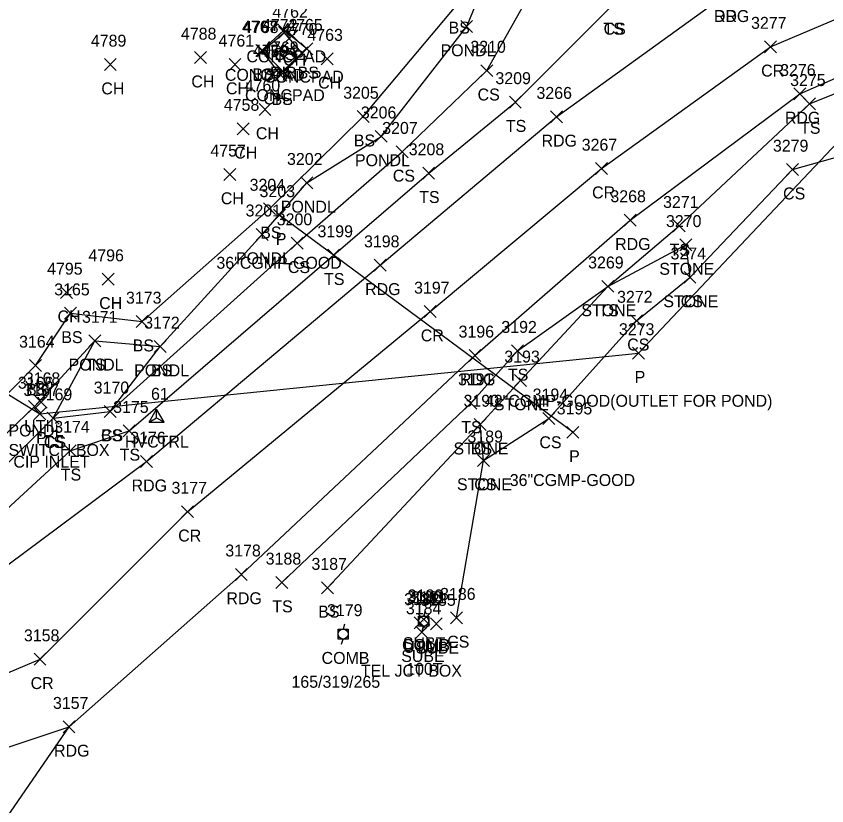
# Model space of a CAD drawing. Extents: x 49137 to 50946, y 9590 to 10709.
# Drawn here: x 50177.5 to 50313.3, y 9667.4 to 9799.7 of the extents above; entities that cross this region are included whole.
import ezdxf

# ---------------------------------------------------------------- set-up
doc = ezdxf.new("R2010")
doc.units = 0
for name, color, linetype in [('C_A', 7, 'Continuous'), ('C_I', 7, 'Continuous'), ('CPSM', 7, 'Continuous'), ('D_A', 7, 'Continuous'), ('D_C', 7, 'Continuous'), ('D_I', 7, 'Continuous'), ('D_TIC', 7, 'Continuous'), ('DCP', 7, 'Continuous'), ('L_A', 7, 'Continuous'), ('L_I', 7, 'Continuous'), ('L_TIC', 7, 'Continuous'), ('LASF', 7, 'Continuous'), ('LAWE', 7, 'Continuous'), ('LELB', 7, 'Continuous'), ('LS', 7, 'Continuous'), ('P_A', 7, 'Continuous'), ('P_I', 7, 'Continuous'), ('P_TIC', 7, 'Continuous'), ('PEU', 7, 'Continuous'), ('PRC', 7, 'Continuous'), ('R_A', 7, 'Continuous'), ('U_A', 7, 'Continuous'), ('U_C', 7, 'Continuous'), ('U_I', 7, 'Continuous'), ('U_TIC', 7, 'Continuous'), ('UDEFAULT', 7, 'Continuous'), ('UP', 7, 'Continuous')]:
    doc.layers.add(name, color=color, linetype=linetype)

msp = doc.modelspace()

# ---------------------------------------------------------------- linework, layer by layer
at = {"layer": 'CPSM'}
for p, q in [((50199.74, 9731.73), (50200.99, 9733.9)), ((50202.24, 9731.73), (50200.99, 9733.9)), ((50200.99, 9732.46), (50200.99, 9733.9)), ((50199.74, 9731.73), (50200.99, 9732.46)), ((50199.74, 9731.73), (50202.24, 9731.73)), ((50200.99, 9732.46), (50200.99, 9732.46)), ((50200.99, 9732.46), (50202.24, 9731.73))]:
    msp.add_line(p, q, dxfattribs=at)
at = {"layer": 'D_TIC'}
for points in [[(50220.91, 9793.29), (50222.91, 9795.29)], [(50222.91, 9793.29), (50220.91, 9795.29)], [(50220.58, 9765.42), (50222.58, 9767.42)], [(50222.58, 9765.42), (50220.58, 9767.42)], [(50280.74, 9742.29), (50282.74, 9744.29)], [(50282.74, 9742.29), (50280.74, 9744.29)], [(50180.4, 9732.09), (50182.4, 9734.09)], [(50182.4, 9732.09), (50180.4, 9734.09)], [(50269.76, 9729.01), (50271.76, 9731.01)], [(50271.76, 9729.01), (50269.76, 9731.01)]]:
    msp.add_lwpolyline(points, dxfattribs=at)
at = {"layer": 'DCP'}
for points in [[(49941.69, 9827.48), (50059.34, 9808.37), (50181.4, 9733.09), (50281.74, 9743.29), (50422.72, 9892.52), (50122.34, 10663.61), (50179.93, 10552.61), (50179.64, 10394.45), (50122.34, 10285.07), (50121.56, 10284.35)], [(50270.76, 9730.01), (50221.58, 9766.42)]]:
    msp.add_lwpolyline(points, dxfattribs=at)
at = {"layer": 'L_TIC'}
for points in [[(50221.31, 9796.39), (50223.31, 9798.39)], [(50223.31, 9796.39), (50221.31, 9798.39)], [(50221.39, 9796.01), (50223.39, 9798.01)], [(50223.39, 9796.01), (50221.39, 9798.01)], [(50221.39, 9796.01), (50223.39, 9798.01)], [(50223.39, 9796.01), (50221.39, 9798.01)], [(50251.96, 9797.03), (50253.96, 9799.03)], [(50253.96, 9797.03), (50251.96, 9799.03)], [(50222.7, 9795.48), (50224.7, 9797.48)], [(50224.7, 9795.48), (50222.7, 9797.48)], [(50225.18, 9793.29), (50227.18, 9795.29)], [(50227.18, 9793.29), (50225.18, 9795.29)], [(50207.32, 9791.81), (50209.32, 9793.81)], [(50209.32, 9791.81), (50207.32, 9793.81)], [(50217.61, 9793), (50219.61, 9795)], [(50219.61, 9793), (50217.61, 9795)], [(50217.61, 9793), (50219.61, 9795)], [(50219.61, 9793), (50217.61, 9795)], [(50217.79, 9792.92), (50219.79, 9794.92)], [(50219.79, 9792.92), (50217.79, 9794.92)], [(50217.79, 9792.92), (50219.79, 9794.92)], [(50219.79, 9792.92), (50217.79, 9794.92)], [(50224.34, 9792.61), (50226.34, 9794.61)], [(50226.34, 9792.61), (50224.34, 9794.61)], [(50192.23, 9790.64), (50194.23, 9792.64)], [(50194.23, 9790.64), (50192.23, 9792.64)], [(50213.12, 9790.66), (50215.12, 9792.66)], [(50215.12, 9790.66), (50213.12, 9792.66)], [(50228.57, 9791.62), (50230.57, 9793.62)], [(50230.57, 9791.62), (50228.57, 9793.62)], [(50221.15, 9789.51), (50223.15, 9791.51)], [(50223.15, 9789.51), (50221.15, 9791.51)], [(50255.35, 9789.62), (50257.35, 9791.62)], [(50257.35, 9789.62), (50255.35, 9791.62)], [(50219.39, 9788.95), (50221.39, 9790.95)], [(50221.39, 9788.95), (50219.39, 9790.95)], [(50220.81, 9788.87), (50222.81, 9790.87)], [(50222.81, 9788.87), (50220.81, 9790.87)], [(50220.81, 9788.87), (50222.81, 9790.87)], [(50222.81, 9788.87), (50220.81, 9790.87)], [(50260.12, 9784.36), (50262.12, 9786.36)], [(50262.12, 9784.36), (50260.12, 9786.36)], [(50309.44, 9784.04), (50311.44, 9786.04)], [(50311.44, 9784.04), (50309.44, 9786.04)], [(50218.15, 9783.13), (50220.15, 9785.13)], [(50220.15, 9783.13), (50218.15, 9785.13)], [(50234.59, 9781.92), (50236.59, 9783.92)], [(50236.59, 9781.92), (50234.59, 9783.92)], [(50214.51, 9779.89), (50216.51, 9781.89)], [(50216.51, 9779.89), (50214.51, 9781.89)], [(50237.61, 9778.61), (50239.61, 9780.61)], [(50239.61, 9778.61), (50237.61, 9780.61)], [(50241.13, 9776.02), (50243.13, 9778.02)], [(50243.13, 9776.02), (50241.13, 9778.02)], [(50306.56, 9773.04), (50308.56, 9775.04)], [(50308.56, 9773.04), (50306.56, 9775.04)], [(50212.26, 9772.23), (50214.26, 9774.23)], [(50214.26, 9772.23), (50212.26, 9774.23)], [(50245.59, 9772.44), (50247.59, 9774.44)], [(50247.59, 9772.44), (50245.59, 9774.44)], [(50225.18, 9770.82), (50227.18, 9772.82)], [(50227.18, 9770.82), (50225.18, 9772.82)], [(50218.91, 9766.49), (50220.91, 9768.49)], [(50220.91, 9766.49), (50218.91, 9768.49)], [(50287.57, 9763.61), (50289.57, 9765.61)], [(50289.57, 9763.61), (50287.57, 9765.61)], [(50217.67, 9762.18), (50219.67, 9764.18)], [(50219.67, 9762.18), (50217.67, 9764.18)], [(50223.55, 9760.7), (50225.55, 9762.7)], [(50225.55, 9760.7), (50223.55, 9762.7)], [(50288.71, 9760.41), (50290.71, 9762.41)], [(50290.71, 9760.41), (50288.71, 9762.41)], [(50229.66, 9758.7), (50231.66, 9760.7)], [(50231.66, 9758.7), (50229.66, 9760.7)], [(50191.87, 9754.67), (50193.87, 9756.67)], [(50193.87, 9754.67), (50191.87, 9756.67)], [(50289.39, 9754.98), (50291.39, 9756.98)], [(50291.39, 9754.98), (50289.39, 9756.98)], [(50289.39, 9754.98), (50291.39, 9756.98)], [(50291.39, 9754.98), (50289.39, 9756.98)], [(50184.89, 9752.43), (50186.89, 9754.43)], [(50186.89, 9752.43), (50184.89, 9754.43)], [(50275.63, 9753.47), (50277.63, 9755.47)], [(50277.63, 9753.47), (50275.63, 9755.47)], [(50275.63, 9753.47), (50277.63, 9755.47)], [(50277.63, 9753.47), (50275.63, 9755.47)], [(50185.56, 9748.96), (50187.56, 9750.96)], [(50187.56, 9748.96), (50185.56, 9750.96)], [(50197.54, 9747.57), (50199.54, 9749.57)], [(50199.54, 9747.57), (50197.54, 9749.57)], [(50280.43, 9747.72), (50282.43, 9749.72)], [(50282.43, 9747.72), (50280.43, 9749.72)], [(50189.61, 9744.36), (50191.61, 9746.36)], [(50191.61, 9744.36), (50189.61, 9746.36)], [(50189.61, 9744.36), (50191.61, 9746.36)], [(50191.61, 9744.36), (50189.61, 9746.36)], [(50200.6, 9743.39), (50202.6, 9745.39)], [(50202.6, 9743.39), (50200.6, 9745.39)], [(50200.6, 9743.39), (50202.6, 9745.39)], [(50202.6, 9743.39), (50200.6, 9745.39)], [(50260.46, 9742.67), (50262.46, 9744.67)], [(50262.46, 9742.67), (50260.46, 9744.67)], [(50179.67, 9740.2), (50181.67, 9742.2)], [(50181.67, 9740.2), (50179.67, 9742.2)], [(50260.97, 9737.7), (50262.97, 9739.7)], [(50262.97, 9737.7), (50260.97, 9739.7)], [(50252.64, 9733.88), (50254.64, 9735.88)], [(50254.64, 9733.88), (50252.64, 9735.88)], [(50179.53, 9733.32), (50181.53, 9735.32)], [(50181.53, 9733.32), (50179.53, 9735.32)], [(50192.22, 9732.51), (50194.22, 9734.51)], [(50194.22, 9732.51), (50192.22, 9734.51)], [(50192.22, 9732.51), (50194.22, 9734.51)], [(50194.22, 9732.51), (50192.22, 9734.51)], [(50182.65, 9731.38), (50184.65, 9733.38)], [(50184.65, 9731.38), (50182.65, 9733.38)], [(50182.65, 9731.38), (50184.65, 9733.38)], [(50184.65, 9731.38), (50182.65, 9733.38)], [(50265.71, 9731.34), (50267.71, 9733.34)], [(50267.71, 9731.34), (50265.71, 9733.34)], [(50195.39, 9729.26), (50197.39, 9731.26)], [(50197.39, 9729.26), (50195.39, 9731.26)], [(50254.2, 9730.3), (50256.2, 9732.3)], [(50256.2, 9730.3), (50254.2, 9732.3)], [(50254.2, 9730.3), (50256.2, 9732.3)], [(50256.2, 9730.3), (50254.2, 9732.3)], [(50185.51, 9725.93), (50187.51, 9727.93)], [(50187.51, 9725.93), (50185.51, 9727.93)], [(50254.79, 9724.3), (50256.79, 9726.3)], [(50256.79, 9724.3), (50254.79, 9726.3)], [(50254.79, 9724.3), (50256.79, 9726.3)], [(50256.79, 9724.3), (50254.79, 9726.3)], [(50220.97, 9703.84), (50222.97, 9705.84)], [(50222.97, 9703.84), (50220.97, 9705.84)], [(50228.63, 9702.96), (50230.63, 9704.96)], [(50230.63, 9702.96), (50228.63, 9704.96)], [(50250.25, 9697.93), (50252.25, 9699.93)], [(50252.25, 9697.93), (50250.25, 9699.93)]]:
    msp.add_lwpolyline(points, dxfattribs=at)
at = {"layer": 'LASF'}
msp.add_lwpolyline([(50255.79, 9725.3), (50255.2, 9731.3), (50261.97, 9738.7), (50276.63, 9754.47), (50289.71, 9761.41), (50290.39, 9755.98)], dxfattribs=at)
at = {"layer": 'LAWE'}
msp.add_lwpolyline([(50126.73, 9813.77), (50124.61, 9796.89), (50111.25, 9777.04), (50110.47, 9750.09), (50103.82, 9729.7), (50104.43, 9724.64), (50098.48, 9698.71), (50117.09, 9681.54), (50135.81, 9695.39), (50163.01, 9717.6), (50180.53, 9734.32), (50190.61, 9745.36), (50201.6, 9744.39), (50218.67, 9763.18), (50226.18, 9771.82), (50238.61, 9779.61), (50252.96, 9798.03), (50263.09, 9822.8), (50257.66, 9841.25), (50250.32, 9860.86)], dxfattribs=at)
at = {"layer": 'LELB'}
for points in [[(49989.46, 9641.11), (50017.53, 9654.36), (50065.13, 9666.04), (50092.49, 9669.85), (50112.07, 9676.7), (50119.45, 9680.62), (50138.81, 9692.31), (50165.23, 9714.09), (50183.65, 9732.38), (50193.22, 9733.51), (50224.55, 9761.7), (50242.13, 9777.02), (50256.35, 9790.62), (50269.01, 9813.23), (50267.22, 9836.46), (50262.07, 9851.46), (50256.24, 9864.61)], [(50130.08, 9813.38), (50127.49, 9796.45), (50115.24, 9773.32), (50112.63, 9748.12), (50107.86, 9731.67), (50105.33, 9723.23), (50101.67, 9703.92), (50120.36, 9686.99), (50133.96, 9697.22), (50159.53, 9719.77), (50180.67, 9741.2), (50186.56, 9749.96), (50198.54, 9748.57), (50219.91, 9767.49), (50235.59, 9782.92), (50251.48, 9801.83), (50259.82, 9821.36), (50255.17, 9839.31), (50246.31, 9858.9)], [(50106.75, 9669.47), (50141.52, 9690.01), (50167.92, 9709.84), (50186.51, 9726.93), (50196.39, 9730.26), (50230.66, 9759.7), (50246.59, 9773.44), (50261.12, 9785.36), (50277.47, 9801.65), (50284.03, 9806.08), (50295.89, 9825.75), (50301.66, 9836.3), (50304.52, 9848.49)], [(50221.81, 9789.87), (50226.18, 9794.29), (50222.31, 9797.39), (50218.61, 9794)], [(50221.81, 9789.87), (50218.61, 9794)], [(50221.97, 9704.84), (50253.64, 9734.88), (50261.46, 9743.67), (50276.63, 9754.47), (50288.57, 9764.61), (50310.44, 9785.04), (50329.97, 9792.93), (50346.68, 9794.33)], [(50251.25, 9698.93), (50255.79, 9725.3), (50266.71, 9732.34), (50281.43, 9748.72), (50290.39, 9755.98), (50307.56, 9774.04), (50325.67, 9779.15), (50338.3, 9776.42), (50346.35, 9772.36)], [(50183.65, 9732.38), (50190.61, 9745.36)], [(50193.22, 9733.51), (50201.6, 9744.39)], [(50229.63, 9703.96), (50255.2, 9731.3)]]:
    msp.add_lwpolyline(points, dxfattribs=at)
at = {"layer": 'LS'}
for points in [[(50218.79, 9793.92), (50222.15, 9790.51), (50225.34, 9793.61), (50222.39, 9797.01)], [(50218.79, 9793.92), (50222.39, 9797.01)]]:
    msp.add_lwpolyline(points, dxfattribs=at)
at = {"layer": 'P_TIC'}
for points in [[(50302.89, 9793.63), (50304.89, 9795.63)], [(50304.89, 9793.63), (50302.89, 9795.63)], [(50307.81, 9785.73), (50309.81, 9787.73)], [(50309.81, 9785.73), (50307.81, 9787.73)], [(50267.02, 9781.89), (50269.02, 9783.89)], [(50269.02, 9781.89), (50267.02, 9783.89)], [(50274.55, 9773.21), (50276.55, 9775.21)], [(50276.55, 9773.21), (50274.55, 9775.21)], [(50279.35, 9764.57), (50281.35, 9766.57)], [(50281.35, 9764.57), (50279.35, 9766.57)], [(50237.44, 9757.01), (50239.44, 9759.01)], [(50239.44, 9757.01), (50237.44, 9759.01)], [(50245.84, 9749.25), (50247.84, 9751.25)], [(50247.84, 9749.25), (50245.84, 9751.25)], [(50253.35, 9741.89), (50255.35, 9743.89)], [(50255.35, 9741.89), (50253.35, 9743.89)], [(50198.31, 9724.1), (50200.31, 9726.1)], [(50200.31, 9724.1), (50198.31, 9726.1)], [(50205.17, 9715.71), (50207.17, 9717.71)], [(50207.17, 9715.71), (50205.17, 9717.71)], [(50214.19, 9705.2), (50216.19, 9707.2)], [(50216.19, 9705.2), (50214.19, 9707.2)], [(50180.44, 9690.98), (50182.44, 9692.98)], [(50182.44, 9690.98), (50180.44, 9692.98)], [(50185.3, 9679.66), (50187.3, 9681.66)], [(50187.3, 9679.66), (50185.3, 9681.66)], [(50185.3, 9679.66), (50187.3, 9681.66)], [(50187.3, 9679.66), (50185.3, 9681.66)]]:
    msp.add_lwpolyline(points, dxfattribs=at)
at = {"layer": 'PEU'}
for points in [[(49941.83, 9610.06), (49990.09, 9639.04), (50024.75, 9652.6), (50065.89, 9663.6), (50106.75, 9669.47), (50143.68, 9687.26), (50173.12, 9705.67), (50199.31, 9725.1), (50238.44, 9758.01), (50268.02, 9782.89), (50296.91, 9803.77), (50321.98, 9815.49), (50335.39, 9819.52), (50365.78, 9821.11), (50382.81, 9823.36), (50421.32, 9824.61), (50445.25, 9815.6), (50461.95, 9809.8), (50483.11, 9806.63), (50497.86, 9807.55), (50514.33, 9805.13), (50518.4, 9805.51), (50536.96, 9801.1)], [(49951.36, 9595.1), (49993.95, 9620.08), (50032.52, 9634.52), (50070.13, 9642.85), (50110.31, 9649.63), (50136.83, 9659.43), (50162.6, 9672.79), (50186.3, 9680.66), (50215.19, 9706.2), (50254.35, 9742.89), (50280.35, 9765.57), (50308.81, 9786.73), (50329.55, 9795.84), (50345.01, 9798.03), (50408.65, 9796.86), (50440.44, 9793.25)], [(50163.23, 9645), (50172.84, 9661.18), (50186.3, 9680.66)]]:
    msp.add_lwpolyline(points, dxfattribs=at)
at = {"layer": 'PRC'}
msp.add_lwpolyline([(49946.14, 9603.32), (49990.57, 9628.34), (50029.06, 9644.26), (50067.71, 9652.16), (50111.82, 9660.88), (50152.59, 9679.83), (50181.44, 9691.98), (50206.17, 9716.71), (50246.84, 9750.25), (50275.55, 9774.21), (50303.89, 9794.63), (50325.93, 9804.02), (50352.75, 9808.7), (50411.41, 9807.82), (50440.83, 9805.17), (50459.62, 9800.88), (50480.38, 9795.99)], dxfattribs=at)
at = {"layer": 'U_TIC'}
for points in [[(50244.76, 9697.67), (50246.76, 9699.67)], [(50246.76, 9697.67), (50244.76, 9699.67)], [(50246.87, 9696.93), (50248.87, 9698.93)], [(50248.87, 9696.93), (50246.87, 9698.93)], [(50244.46, 9695.52), (50246.46, 9697.52)], [(50246.46, 9695.52), (50244.46, 9697.52)]]:
    msp.add_lwpolyline(points, dxfattribs=at)
at = {"layer": 'UDEFAULT'}
for points in [[(50180.63, 9734.05), (50182.63, 9736.05)], [(50182.63, 9734.05), (50180.63, 9736.05)], [(50244.16, 9697.06), (50246.16, 9699.06)], [(50246.16, 9697.06), (50244.16, 9699.06)]]:
    msp.add_lwpolyline(points, dxfattribs=at)
at = {"layer": 'UP'}
for p, q in [((50245.99, 9700.04), (50245.74, 9699.2)), ((50246.01, 9700.04), (50245.76, 9699.2)), ((50244.9, 9697.54), (50244.9, 9699.2)), ((50244.9, 9699.2), (50246.57, 9699.2)), ((50244.92, 9697.54), (50244.92, 9699.2)), ((50244.92, 9699.2), (50246.59, 9699.2)), ((50246.57, 9699.2), (50246.57, 9697.54)), ((50246.59, 9699.2), (50246.59, 9697.54)), ((50232.5, 9697.87), (50232.25, 9697.03)), ((50246.57, 9697.54), (50244.9, 9697.54)), ((50246.59, 9697.54), (50244.92, 9697.54)), ((50245.49, 9696.7), (50245.74, 9697.54)), ((50245.51, 9696.7), (50245.76, 9697.54)), ((50245.74, 9698.37), (50245.74, 9698.37)), ((50245.76, 9698.37), (50245.76, 9698.37)), ((50231.42, 9695.37), (50231.42, 9697.03)), ((50231.42, 9697.03), (50233.09, 9697.03)), ((50232.25, 9696.2), (50232.25, 9696.2)), ((50233.09, 9697.03), (50233.09, 9695.37)), ((50233.09, 9695.37), (50231.42, 9695.37)), ((50232, 9694.53), (50232.25, 9695.37))]:
    msp.add_line(p, q, dxfattribs=at)
for centre in [(50245.74, 9698.37), (50245.76, 9698.37), (50232.25, 9696.2)]:
    msp.add_circle(centre, 0.833, dxfattribs=at)

# ---------------------------------------------------------------- texts
at = {"layer": 'C_A'}
msp.add_text('HVCTRL', height=2, dxfattribs=at).set_placement((50195.68, 9727.46))
at = {"layer": 'C_I'}
msp.add_text('61', height=2, dxfattribs=at).set_placement((50200.05, 9735.46))
at = {"layer": 'D_A'}
for s, p in [('DIB', (50220.01, 9789.29)), ('P', (50220.96, 9761.42)), ('P', (50281.12, 9738.29)), ('P', (50180.78, 9728.09)), ('P', (50270.13, 9725.01))]:
    msp.add_text(s, height=2, dxfattribs=at).set_placement(p)
at = {"layer": 'D_C'}
for s, p in [('36"CGMP-GOOD', (50211.01, 9757.42)), ('42"CGMP-GOOD(OUTLET FOR POND)', (50256.01, 9734.29)), ('12" CIP INLET', (50172.31, 9724.09)), ('36"CGMP-GOOD', (50260.18, 9721.01))]:
    msp.add_text(s, height=2, dxfattribs=at).set_placement(p)
at = {"layer": 'D_I'}
for s, p in [('4772', (50218.65, 9797.29)), ('3203', (50218.24, 9769.42)), ('3273', (50278.48, 9746.29)), ('3167', (50178.66, 9736.09)), ('3195', (50268.06, 9733.01))]:
    msp.add_text(s, height=2, dxfattribs=at).set_placement(p)
at = {"layer": 'L_A'}
for s, p in [('BS', (50249.93, 9796.83)), ('TS', (50275.88, 9796.65)), ('CS', (50275.91, 9796.65)), ('CONCPAD', (50216.04, 9792.01)), ('CONCPAD', (50216.04, 9792.01)), ('BS', (50220.75, 9792.39)), ('PONDL', (50248.58, 9793.03)), ('CH', (50222.19, 9791.48)), ('BS', (50217.05, 9789)), ('BS', (50217.05, 9789)), ('BS', (50224.62, 9789.29)), ('CH', (50206.81, 9787.81)), ('CONCPAD', (50212.43, 9788.92)), ('CONCPAD', (50212.43, 9788.92)), ('CONCPAD', (50218.98, 9788.61)), ('CH', (50191.72, 9786.64)), ('CH', (50212.61, 9786.66)), ('CH', (50228.06, 9787.62)), ('CONCPAD', (50215.8, 9785.51)), ('CH', (50218.88, 9784.95)), ('CS', (50254.79, 9785.62)), ('BS', (50220.25, 9784.87)), ('BS', (50220.25, 9784.87)), ('TS', (50259.53, 9780.36)), ('TS', (50308.85, 9780.04)), ('CH', (50217.63, 9779.13)), ('BS', (50234.04, 9777.92)), ('CH', (50214, 9775.89)), ('PONDL', (50234.23, 9774.61)), ('CS', (50240.58, 9772.02)), ('CS', (50306, 9769.04)), ('CH', (50211.75, 9768.23)), ('TS', (50245, 9768.44)), ('PONDL', (50221.8, 9766.82)), ('BS', (50218.35, 9762.49)), ('TS', (50286.98, 9759.61)), ('PONDL', (50214.29, 9758.18)), ('CS', (50222.99, 9756.7)), ('STONE', (50285.25, 9756.41)), ('TS', (50229.06, 9754.7)), ('STONE', (50285.93, 9750.98)), ('CS', (50288.83, 9750.98)), ('CH', (50191.36, 9750.67)), ('CH', (50184.38, 9748.43)), ('STONE', (50272.18, 9749.47)), ('TS', (50275.04, 9749.47)), ('BS', (50185.01, 9744.96)), ('BS', (50196.98, 9743.57)), ('CS', (50279.87, 9743.72)), ('PONDL', (50186.23, 9740.36)), ('TS', (50189.02, 9740.36)), ('PONDL', (50197.22, 9739.39)), ('BS', (50200.04, 9739.39)), ('TS', (50259.87, 9738.67)), ('BS', (50179.11, 9736.2)), ('STONE', (50257.51, 9733.7)), ('PONDL', (50176.15, 9729.32)), ('TS', (50252.05, 9729.88)), ('CS', (50191.66, 9728.51)), ('BS', (50191.66, 9728.51)), ('TS', (50182.06, 9727.38)), ('CS', (50182.09, 9727.38)), ('CS', (50265.15, 9727.34)), ('TS', (50194.8, 9725.26)), ('STONE', (50250.75, 9726.3)), ('BS', (50253.65, 9726.3)), ('TS', (50184.92, 9721.93)), ('STONE', (50251.33, 9720.3)), ('CS', (50254.23, 9720.3)), ('TS', (50220.38, 9699.84)), ('BS', (50228.07, 9698.96)), ('CS', (50249.69, 9693.93))]:
    msp.add_text(s, height=2, dxfattribs=at).set_placement(p)
at = {"layer": 'L_I'}
for s, p in [('4762', (50220.39, 9799.48)), ('4765', (50222.88, 9797.29)), ('4788', (50205.06, 9795.81)), ('4767', (50215.3, 9797)), ('4767', (50215.3, 9797)), ('4768', (50215.48, 9796.92)), ('4768', (50215.48, 9796.92)), ('4770', (50221.99, 9796.61)), ('4789', (50189.96, 9794.64)), ('4761', (50211.38, 9794.66)), ('4763', (50226.26, 9795.62)), ('4769', (50218.84, 9793.51)), ('3210', (50253.57, 9793.62)), ('4759', (50217.12, 9792.95)), ('4764', (50218.5, 9792.87)), ('4764', (50218.5, 9792.87)), ('3209', (50257.78, 9788.36)), ('3275', (50307.18, 9788.04)), ('4760', (50215.75, 9787.13)), ('3205', (50232.26, 9785.92)), ('4758', (50212.25, 9783.89)), ('3206', (50235.22, 9782.61)), ('3207', (50238.8, 9780.02)), ('3279', (50304.29, 9777.04)), ('4757', (50210, 9776.23)), ('3208', (50243.25, 9776.44)), ('3202', (50222.84, 9774.82)), ('3204', (50216.57, 9770.49)), ('3271', (50285.88, 9767.61)), ('3201', (50215.9, 9766.18)), ('3200', (50221.12, 9764.7)), ('3270', (50286.36, 9764.41)), ('3199', (50227.95, 9762.7)), ('4796', (50189.55, 9758.67)), ('3274', (50287.13, 9758.98)), ('3274', (50287.13, 9758.98)), ('4795', (50182.63, 9756.43)), ('3269', (50273.32, 9757.47)), ('3269', (50273.32, 9757.47)), ('3165', (50183.82, 9752.96)), ('3173', (50195.85, 9751.57)), ('3272', (50278.17, 9751.72)), ('3171', (50188.48, 9748.36)), ('3171', (50188.48, 9748.36)), ('3172', (50198.9, 9747.39)), ('3172', (50198.9, 9747.39)), ('3192', (50258.77, 9746.67)), ('3164', (50177.93, 9744.2)), ('3193', (50259.27, 9741.7)), ('3191', (50251.51, 9737.88)), ('3166', (50177.73, 9737.32)), ('3170', (50190.44, 9736.51)), ('3170', (50190.44, 9736.51)), ('3169', (50180.9, 9735.38)), ('3169', (50180.9, 9735.38)), ('3194', (50264.02, 9735.34)), ('3190', (50252.43, 9734.3)), ('3190', (50252.43, 9734.3)), ('3175', (50193.7, 9733.26)), ('3174', (50183.82, 9729.93)), ('3189', (50253.09, 9728.3)), ('3189', (50253.09, 9728.3)), ('3188', (50219.27, 9707.84)), ('3187', (50226.94, 9706.96)), ('3186', (50248.5, 9701.93))]:
    msp.add_text(s, height=2, dxfattribs=at).set_placement(p)
at = {"layer": 'P_A'}
for s, p in [('RDG', (50294.4, 9798.77)), ('CR', (50302.32, 9789.63)), ('RDG', (50306.3, 9781.73)), ('RDG', (50265.51, 9777.89)), ('CR', (50273.98, 9769.21)), ('RDG', (50277.84, 9760.57)), ('RDG', (50235.93, 9753.01)), ('CR', (50245.27, 9745.25)), ('RDG', (50251.84, 9737.89)), ('RDG', (50196.79, 9720.1)), ('CR', (50204.6, 9711.71)), ('RDG', (50212.68, 9701.2)), ('CR', (50179.87, 9686.98)), ('RDG', (50183.79, 9675.66)), ('RDG', (50183.79, 9675.66))]:
    msp.add_text(s, height=2, dxfattribs=at).set_placement(p)
at = {"layer": 'P_I'}
for s, p in [('3277', (50300.63, 9797.63)), ('3276', (50305.5, 9789.73)), ('3266', (50264.66, 9785.89)), ('3267', (50272.24, 9777.21)), ('3268', (50277.05, 9768.57)), ('3198', (50235.75, 9761.01)), ('3197', (50244.14, 9753.25)), ('3196', (50251.6, 9745.89)), ('3176', (50196.56, 9728.1)), ('3177', (50203.48, 9719.71)), ('3178', (50212.5, 9709.2)), ('3158', (50178.74, 9694.98)), ('3157', (50183.61, 9683.66)), ('3157', (50183.61, 9683.66))]:
    msp.add_text(s, height=2, dxfattribs=at).set_placement(p)
at = {"layer": 'R_A'}
msp.add_text('DRG', height=2, dxfattribs=at).set_placement((50294.4, 9798.77))
at = {"layer": 'U_A'}
for s, p in [('UTIL', (50178.79, 9730.05)), ('COMB', (50242.12, 9693.37)), ('COMB', (50242.14, 9693.37)), ('SUBT', (50242.26, 9693.67)), ('UTIL', (50242.33, 9693.06)), ('SUBE', (50244.41, 9692.93)), ('COMB', (50228.64, 9691.2)), ('SUBE', (50241.99, 9691.52))]:
    msp.add_text(s, height=2, dxfattribs=at).set_placement(p)
at = {"layer": 'U_C'}
for s, p in [('ELEC SWITCH BOX', (50168.43, 9726.05)), ('TEL JCT BOX', (50235.22, 9689.06)), ('100T', (50242.82, 9689.37)), ('165/319/265', (50223.59, 9687.2))]:
    msp.add_text(s, height=2, dxfattribs=at).set_placement(p)
at = {"layer": 'U_I'}
for s, p in [('3168', (50178.89, 9738.05)), ('3182', (50242.47, 9701.06)), ('3180', (50242.96, 9701.37)), ('3183', (50243.07, 9701.67)), ('3181', (50243.63, 9701.37)), ('3185', (50245.18, 9700.93)), ('3184', (50242.77, 9699.52)), ('3179', (50229.55, 9699.2))]:
    msp.add_text(s, height=2, dxfattribs=at).set_placement(p)

doc.saveas('drawing.dxf')
